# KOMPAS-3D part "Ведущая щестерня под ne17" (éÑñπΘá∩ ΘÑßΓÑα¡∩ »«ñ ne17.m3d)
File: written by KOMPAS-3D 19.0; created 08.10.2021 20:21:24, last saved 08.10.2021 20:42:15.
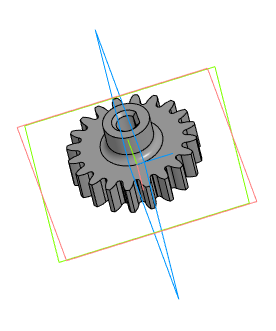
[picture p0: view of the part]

Document properties: Автор: Дымок(R); Организация: PDA-NN.3dn.ru; Полное имя файла: D:\3D_print\3D проекты Компас 3D\Халява Projects 5\Ведущая щестерня под ne17.m3d

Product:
- Part/product: Ведущая щестерня под ne17
    Масса: 0.0483297

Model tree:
1. ЛСК (Шестерня цилиндрическая с внешними зубьями):1  (with: Шестерня цилиндрическая с внешними зубьями:1, Плоскость XY, Плоскость ZX, Плоскость ZY, Ось X, Ось Y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)  (labels: &Фаска (Шестерня цилиндрическая с внешними зубьями):1)
     Ось X. X = 1; Ось Y. Y = 1; Ось Z. Z = 1; Угол 1 = 360
2. Эскиз для винтовой линии (Шестерня цилиндрическая с внешними зубьями):1  (with: Винтовая линия (Шестерня цилиндрическая с внешними зубьями):1, Шестерня цилиндрическая с внешними зубьями:1, Впадина прямая (Шестерня цилиндрическая с внешними зубьями):1, Впадина косая (Шестерня цилиндрическая с внешними зубьями):1, Массив впадин (Шестерня цилиндрическая с внешними зубьями):1)  (2 pattern instances)
     Число витков = 0.00742627; Смещение 2 = 8
3. Впадина прямая (Шестерня цилиндрическая с внешними зубьями):1  (with: Массив впадин (Шестерня цилиндрическая с внешними зубьями):1, Шестерня цилиндрическая с внешними зубьями:1)  (20 pattern instances)
     N 1 = 1; Шаг 1 = 1; Номер 1 = 1
4. Впадина косая (Шестерня цилиндрическая с внешними зубьями):1  (with: Винтовая линия (Шестерня цилиндрическая с внешними зубьями):1)
     N 1 = 1; Шаг 1 = 1; Номер 1 = 1
5. Шестерня цилиндрическая с внешними зубьями:1
6. Эскиз:5  (with: Цилиндр (Шестерня цилиндрическая с внешними зубьями):1, Впадина прямая (Шестерня цилиндрическая с внешними зубьями):1)
7. Элемент выдавливания:3
8. Эскиз:6  (with: Цилиндр (Шестерня цилиндрическая с внешними зубьями):1, Элемент выдавливания:3)
9. Элемент выдавливания:4
     Расстояние 1 = 8
10. Скругление:1  (with: Элемент выдавливания:4)
     Радиус = 2
11. Фаска:2  (with: Элемент выдавливания:4)
     Угол = 45; Длина 1 = 1; Длина 2 = 1

Expressions: (VGExtS_1_z*VGExtS_1_M)/COSD(VGExtS_1_Beta); 360/VGExtS_1_z
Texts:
  SHAFT3D
  Количество отображаемых зубьев
  Угол наклона линии зубьев
  Шаг по кольцевому направлению
  (VGExtS_1_Beta>0)?(M_PI*VGExtS_1_z*VGExtS_1_M/SIND(VGExtS_1_Beta)):1000
  (VGExtS_1_Da<=0||VGExtS_1_Da>5e+7)?25:VGExtS_1_Da
  (VGExtS_1_H<=0||VGExtS_1_H>5e+7)?25:VGExtS_1_H
  VGExtS_1_zz<VGExtS_1_z?(VGExtS_1_zz+1):VGExtS_1_z
  (VGExtS_1_zz<=0||VGExtS_1==1)||(VGExtS_1_Beta>0)?1:0
  (VGExtS_1_zz<=0||VGExtS_1==1)||(VGExtS_1_Beta<=0)?1:0
  (VGExtS_1==1)||(VGExtS_1_Beta<=0)?1:0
